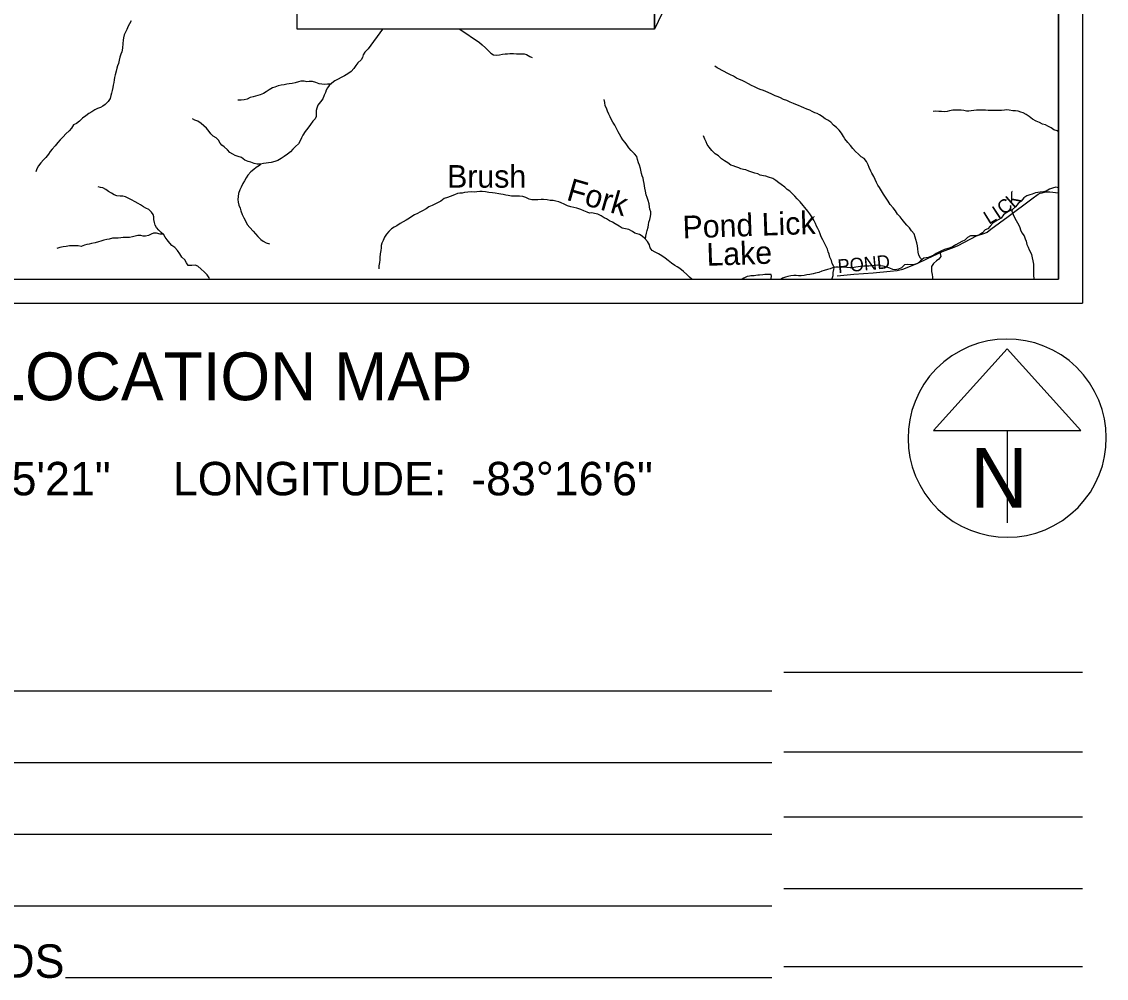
# Model space of a CAD drawing. Extents: x 0 to 34, y 0 to 22.
# Drawn here: x 4.561 to 9.099, y 11.175 to 15.178 of the extents above; entities that cross this region are included whole.
import ezdxf

# ---------------------------------------------------------------- set-up
doc = ezdxf.new("R2010")
doc.units = 0
for name, color, linetype in [('Default', 7, 'Continuous'), ('GM_X_Minor_Lake', 7, 'Continuous'), ('GM_X_Minor_Lake_Text', 7, 'Continuous'), ('GM_X_Minor_River', 7, 'Continuous'), ('GM_X_Minor_River_Text', 7, 'Continuous'), ('GM_X_Township_Road', 7, 'Continuous'), ('GM_X_Township_Road_Text', 7, 'Continuous'), ('SH_Cut_Line', 7, 'Continuous'), ('SH_Data', 7, 'Continuous'), ('SH_Text', 7, 'Continuous')]:
    doc.layers.add(name, color=color, linetype=linetype)

msp = doc.modelspace()

# ---------------------------------------------------------------- linework, layer by layer
at = {"layer": 'Default'}
msp.add_lwpolyline([(2.4545, 17.2795), (2.4313, 15.0183), (2.4372, 14.2719), (2.4352, 14.1), (8.9, 14.1), (8.9, 18.9397)], dxfattribs=at)
at = {"layer": 'GM_X_Minor_Lake'}
msp.add_lwpolyline([(7.6973, 14.1), (7.6976, 14.1032), (7.6984, 14.1127), (7.6969, 14.1207), (7.6886, 14.1207), (7.6802, 14.1204), (7.6711, 14.1197), (7.6616, 14.1186), (7.649, 14.1175), (7.641, 14.1168), (7.633, 14.1157), (7.6266, 14.115), (7.6209, 14.1147), (7.6117, 14.114), (7.606, 14.1136), (7.5969, 14.1118), (7.5885, 14.1073), (7.5824, 14.1042), (7.5756, 14.1)], dxfattribs=at)
at = {"layer": 'GM_X_Minor_River'}
for points in [[(5.0199, 15.1817), (5.013, 15.1696), (5.0076, 15.1597), (5.001, 15.1453), (4.9953, 15.1336), (4.9899, 15.123), (4.9868, 15.1109), (4.9859, 15.1014), (4.9851, 15.0869), (4.9827, 15.0672), (4.9803, 15.052), (4.9764, 15.0422), (4.9722, 15.0297), (4.9698, 15.0175), (4.9659, 15.0035), (4.9624, 14.9929), (4.9601, 14.983), (4.9566, 14.9717), (4.9527, 14.9561), (4.9504, 14.9444), (4.9484, 14.9341), (4.9472, 14.9239), (4.9448, 14.9121), (4.9429, 14.9026), (4.9394, 14.8901), (4.9374, 14.8787), (4.9343, 14.8689), (4.9312, 14.8567), (4.9231, 14.8435), (4.9113, 14.8322), (4.9013, 14.8243), (4.891, 14.8194), (4.8781, 14.8145), (4.8678, 14.8089), (4.8544, 14.8002), (4.8418, 14.7938), (4.8292, 14.784), (4.8159, 14.7739), (4.8029, 14.7618), (4.7903, 14.7527), (4.7781, 14.746), (4.7696, 14.7327), (4.7597, 14.7214), (4.7459, 14.7089), (4.7344, 14.6965), (4.7229, 14.6836), (4.7133, 14.6719), (4.7011, 14.6587), (4.6888, 14.6451), (4.6808, 14.6345), (4.6735, 14.6243), (4.6628, 14.6095), (4.6532, 14.6001), (4.6417, 14.5876), (4.6318, 14.5748), (4.6248, 14.5619), (4.6202, 14.5498)], [(6.071, 15.147), (6.0105, 15.0644), (5.9971, 15.0508), (5.9906, 15.0387), (5.9867, 15.0289), (5.9813, 15.0183), (5.9683, 15.0062), (5.9599, 14.9952), (5.9511, 14.9816), (5.9396, 14.9695), (5.9255, 14.9593), (5.9125, 14.9514), (5.8984, 14.9443), (5.8854, 14.9375), (5.8721, 14.9304), (5.8591, 14.9206), (5.8472, 14.9112), (5.8415, 14.9013), (5.8353, 14.8915), (5.8319, 14.882), (5.8268, 14.8699), (5.8207, 14.8555), (5.8118, 14.8423), (5.8004, 14.8286), (5.7957, 14.8161), (5.7941, 14.8063), (5.7929, 14.7941), (5.794, 14.782), (5.789, 14.771), (5.779, 14.7612), (5.7694, 14.7479), (5.7583, 14.7328), (5.7468, 14.7188), (5.7372, 14.7037), (5.7326, 14.6919), (5.7268, 14.6791), (5.7199, 14.667), (5.7073, 14.6556), (5.6954, 14.6443), (5.6855, 14.6341), (5.6732, 14.6232), (5.6595, 14.6138), (5.6465, 14.6051), (5.6335, 14.5976), (5.6202, 14.5923), (5.6046, 14.5886), (5.5939, 14.5875), (5.5844, 14.5865), (5.573, 14.5842), (5.5601, 14.582), (5.5471, 14.5821), (5.5339, 14.5848), (5.5206, 14.5895), (5.5088, 14.5933), (5.4952, 14.5984), (5.4812, 14.6098), (5.4671, 14.6145), (5.4543, 14.6187), (5.4448, 14.6233), (5.4327, 14.6302), (5.4225, 14.6413), (5.4089, 14.6539), (5.399, 14.6608), (5.3919, 14.6703), (5.3847, 14.6821), (5.3756, 14.6917), (5.3631, 14.699), (5.3526, 14.7089), (5.3465, 14.7188), (5.3352, 14.7322)], [(6.3947, 15.147), (6.4771, 15.0906), (6.4885, 15.0807), (6.5013, 15.0685), (6.5149, 15.0562), (6.5244, 15.0467), (6.5353, 15.0394), (6.5479, 15.0382), (6.5604, 15.04), (6.5726, 15.0423), (6.584, 15.0441), (6.5935, 15.044), (6.6034, 15.0444), (6.6186, 15.045), (6.6312, 15.0442), (6.6414, 15.0438), (6.6513, 15.0441), (6.6638, 15.0429), (6.6741, 15.0409), (6.687, 15.0321), (6.6968, 15.0283)], [(8.3282, 14.1824), (8.322, 14.1882), (8.3148, 14.2004), (8.3119, 14.2137), (8.3112, 14.2274), (8.309, 14.2407), (8.306, 14.2532), (8.3019, 14.2665), (8.2997, 14.276), (8.2949, 14.2901), (8.2847, 14.3023), (8.2764, 14.3149), (8.2654, 14.3271), (8.2564, 14.3367), (8.2454, 14.3508), (8.2375, 14.3611), (8.2258, 14.3729), (8.2179, 14.3859), (8.2074, 14.3992), (8.1949, 14.4126), (8.1862, 14.4263), (8.178, 14.44), (8.1674, 14.4568), (8.1588, 14.4705), (8.1505, 14.4842), (8.143, 14.4945), (8.1381, 14.5052), (8.1321, 14.517), (8.1261, 14.5303), (8.1189, 14.5437), (8.1137, 14.5532), (8.1077, 14.5673), (8.1024, 14.5794), (8.0961, 14.5928), (8.0863, 14.605), (8.0734, 14.6123), (8.062, 14.6233), (8.0496, 14.6348), (8.039, 14.6478), (8.0296, 14.6604), (8.0186, 14.673), (8.0058, 14.6875), (7.9998, 14.6981), (7.9919, 14.7115), (7.9813, 14.7244), (7.97, 14.7348), (7.9579, 14.7447), (7.9466, 14.7569), (7.9341, 14.7653), (7.9235, 14.7722), (7.911, 14.7818), (7.8992, 14.7887), (7.8898, 14.7937), (7.8799, 14.7972), (7.8689, 14.8022), (7.8591, 14.8075), (7.8466, 14.8122), (7.8337, 14.8176), (7.8242, 14.8222), (7.8113, 14.8272), (7.8007, 14.831), (7.7901, 14.8364), (7.7768, 14.8418), (7.7624, 14.848), (7.7491, 14.853), (7.7362, 14.8591), (7.7268, 14.8637), (7.7135, 14.8684), (7.7002, 14.8745), (7.6847, 14.8822), (7.6748, 14.886), (7.6646, 14.8899), (7.6509, 14.8949), (7.6407, 14.8991), (7.627, 14.9061), (7.6149, 14.9107), (7.602, 14.918), (7.5865, 14.9264), (7.5755, 14.9318), (7.5645, 14.936), (7.5524, 14.9418), (7.5391, 14.9495), (7.5266, 14.956), (7.513, 14.9621), (7.5005, 14.9694), (7.4717, 14.9848), (7.4618, 14.9917)], [(5.8538, 14.9164), (5.8408, 14.9165), (5.8286, 14.9154), (5.8165, 14.9167), (5.8059, 14.9182), (5.7922, 14.9229), (5.7782, 14.9279), (5.7645, 14.928), (5.7538, 14.9269), (5.7436, 14.9296), (5.7295, 14.9285), (5.7192, 14.9259), (5.7063, 14.9222), (5.6934, 14.92), (5.6812, 14.9178), (5.6709, 14.916), (5.6595, 14.9138), (5.6469, 14.9119), (5.6344, 14.909), (5.621, 14.9045), (5.6107, 14.9019), (5.5974, 14.8928), (5.5836, 14.8842), (5.573, 14.8774), (5.5585, 14.8714), (5.549, 14.8692), (5.5394, 14.8666), (5.5299, 14.8636), (5.5177, 14.861), (5.5048, 14.8543), (5.4922, 14.8517), (5.4793, 14.8502), (5.4664, 14.8503)], [(7.1711, 14.2681), (7.1734, 14.2801), (7.1757, 14.2934), (7.1781, 14.3044), (7.1831, 14.3177), (7.1835, 14.3283), (7.1855, 14.3397), (7.189, 14.3503), (7.1925, 14.3632), (7.1937, 14.3727), (7.193, 14.3825), (7.1897, 14.3932), (7.1878, 14.4027), (7.1868, 14.4156), (7.1827, 14.4293), (7.1778, 14.443), (7.1745, 14.4533), (7.1708, 14.4692), (7.1686, 14.4818), (7.1675, 14.4917), (7.1664, 14.5012), (7.1631, 14.5137), (7.1612, 14.5236), (7.1579, 14.5331), (7.1553, 14.543), (7.1508, 14.5643), (7.146, 14.5776), (7.1422, 14.5879), (7.1385, 14.6012), (7.1352, 14.6138), (7.1257, 14.6252), (7.1118, 14.6397), (7.1023, 14.6496), (7.0933, 14.6622), (7.0861, 14.6725), (7.0759, 14.6843), (7.0699, 14.6943), (7.062, 14.7068), (7.0564, 14.7175), (7.0504, 14.7316), (7.0425, 14.7453), (7.0353, 14.7571), (7.0278, 14.7708), (7.0229, 14.7803), (7.0177, 14.7906), (7.0117, 14.8032), (7.008, 14.8165), (7.0031, 14.826), (7.0013, 14.8405), (6.9979, 14.8526)], [(8.9, 14.7176), (8.894, 14.7208), (8.8804, 14.7262), (8.8683, 14.7339), (8.8546, 14.7412), (8.8452, 14.7461), (8.8326, 14.7496), (8.8194, 14.7558), (8.8053, 14.7612), (8.7902, 14.7704), (8.7762, 14.7807), (8.7645, 14.7899), (8.7519, 14.796), (8.7421, 14.7999), (8.7303, 14.8038), (8.7189, 14.8053), (8.7079, 14.8054), (8.6935, 14.8074), (8.6836, 14.809), (8.6737, 14.8075), (8.6615, 14.8064), (8.652, 14.8061), (8.6186, 14.8063), (8.6049, 14.8071), (8.5935, 14.8076), (8.5566, 14.8078), (8.5445, 14.8067), (8.5342, 14.8049), (8.5235, 14.8034), (8.514, 14.8038), (8.5026, 14.8058), (8.4924, 14.8074), (8.4814, 14.8074), (8.4673, 14.8079), (8.4567, 14.8076), (8.4433, 14.8046), (8.4334, 14.8016), (8.4235, 14.8013), (8.4099, 14.8021), (8.3981, 14.8022), (8.3863, 14.8034), (8.3749, 14.802)], [(5.3352, 14.7322), (5.3239, 14.7417), (5.3125, 14.752), (5.2989, 14.7616), (5.2856, 14.7659), (5.2762, 14.7712)], [(7.9626, 14.1497), (7.9587, 14.153), (7.9527, 14.166), (7.949, 14.1789), (7.943, 14.1926), (7.9393, 14.2048), (7.9363, 14.2143), (7.9326, 14.2265), (7.9262, 14.2398), (7.9194, 14.2535), (7.9134, 14.2649), (7.9066, 14.2783), (7.9025, 14.2908), (7.8984, 14.3011), (7.8924, 14.3121), (7.8875, 14.3228), (7.8823, 14.3338), (7.8763, 14.3479), (7.8673, 14.3609), (7.8594, 14.3746), (7.8511, 14.3853), (7.8382, 14.3998), (7.8311, 14.4093), (7.8186, 14.4238), (7.8065, 14.4364), (7.7956, 14.4483), (7.7865, 14.4578), (7.7752, 14.4689), (7.7646, 14.4765), (7.754, 14.4853), (7.7393, 14.4968), (7.7294, 14.5041), (7.7162, 14.5129), (7.7048, 14.5221), (7.6858, 14.5275), (7.6745, 14.5314), (7.6646, 14.5325), (7.6517, 14.5357), (7.6415, 14.5414), (7.6286, 14.5445), (7.616, 14.548), (7.6043, 14.5519), (7.591, 14.5576), (7.5808, 14.56), (7.5709, 14.5623), (7.5614, 14.5658), (7.5493, 14.5704), (7.5379, 14.5747), (7.528, 14.5781), (7.5152, 14.5877), (7.5023, 14.5957), (7.4898, 14.6042), (7.4762, 14.6164), (7.4629, 14.6252), (7.449, 14.6386), (7.4384, 14.6523), (7.4294, 14.6645), (7.4245, 14.6748), (7.4196, 14.687), (7.4136, 14.7003)], [(5.5638, 14.5827), (5.557, 14.5764), (5.5429, 14.5677), (5.5329, 14.559), (5.52, 14.5504), (5.5077, 14.5356), (5.5012, 14.5243), (5.4931, 14.5118), (5.487, 14.5012), (5.4793, 14.4849), (5.4742, 14.4747), (5.4692, 14.4595), (5.4665, 14.4462), (5.4664, 14.4341), (5.4678, 14.4234), (5.4704, 14.4109), (5.4749, 14.398), (5.4779, 14.3869), (5.4835, 14.3713), (5.4906, 14.3576), (5.4981, 14.3443), (5.5053, 14.3298), (5.5162, 14.3161), (5.5305, 14.3019), (5.5403, 14.2897), (5.549, 14.2798), (5.5619, 14.2668), (5.5717, 14.2596), (5.5846, 14.2527), (5.5979, 14.248)], [(4.9735, 14.4483), (4.9598, 14.4495), (4.9484, 14.4537), (4.9374, 14.4606), (4.9242, 14.4679), (4.9139, 14.4756), (4.9011, 14.4821), (4.8916, 14.4848), (4.8817, 14.4864)], [(8.9, 14.4825), (8.8876, 14.4858), (8.8746, 14.4809), (8.8617, 14.4772), (8.848, 14.4693), (8.8362, 14.4667), (8.8225, 14.4641), (8.8129, 14.463), (8.8031, 14.4612), (8.7897, 14.4567), (8.7798, 14.4533), (8.7669, 14.4492), (8.7539, 14.4413), (8.7432, 14.4273), (8.7305, 14.4172), (8.7198, 14.4035), (8.7072, 14.3926), (8.6935, 14.3855), (8.6801, 14.3783), (8.6694, 14.3693), (8.6598, 14.3564), (8.6469, 14.3489), (8.6369, 14.3436), (8.624, 14.335), (8.614, 14.3221), (8.6033, 14.3115), (8.5926, 14.307), (8.5819, 14.2946), (8.5704, 14.287), (8.5575, 14.2826), (8.5453, 14.2822), (8.5316, 14.2823), (8.5179, 14.2752), (8.5076, 14.2639)], [(5.3478, 14.1), (5.3461, 14.1067), (5.3378, 14.1192), (5.3242, 14.1315), (5.3117, 14.1426), (5.2989, 14.1544), (5.2867, 14.159), (5.2727, 14.1572), (5.2586, 14.1584), (5.2507, 14.1695), (5.2435, 14.1813), (5.2314, 14.1931), (5.2224, 14.2061), (5.213, 14.2202), (5.2028, 14.2324), (5.1899, 14.2408), (5.1816, 14.2515), (5.1703, 14.2656), (5.1624, 14.2759), (5.156, 14.2855), (5.1447, 14.2962), (5.1349, 14.305), (5.1258, 14.3164), (5.1205, 14.3267), (5.1164, 14.3381), (5.1146, 14.3503), (5.1139, 14.3617), (5.1113, 14.3712), (5.1049, 14.3807), (5.0932, 14.3918), (5.0815, 14.3979), (5.0716, 14.4037), (5.0587, 14.4117), (5.0489, 14.4171), (5.036, 14.424), (5.0209, 14.4328), (4.9959, 14.4451), (4.9852, 14.4475), (4.9735, 14.4483)], [(7.3647, 14.1), (7.3559, 14.1089), (7.3438, 14.1204), (7.3306, 14.1323), (7.3147, 14.1453), (7.3037, 14.1518), (7.2938, 14.1583), (7.2798, 14.1671), (7.2666, 14.1782), (7.2541, 14.1878), (7.2401, 14.1977), (7.2257, 14.2061), (7.2117, 14.2138), (7.1992, 14.2207), (7.1905, 14.2314), (7.1883, 14.2447), (7.1801, 14.2588), (7.1684, 14.271), (7.1578, 14.281), (7.146, 14.2879), (7.1362, 14.2898), (7.1263, 14.2937), (7.1165, 14.3002), (7.1021, 14.3079), (7.0876, 14.311), (7.0744, 14.3145), (7.0611, 14.3225), (7.0444, 14.3325), (7.0327, 14.339), (7.0213, 14.3451), (7.0077, 14.3524), (6.9982, 14.3574), (6.9857, 14.3655), (6.9717, 14.3732), (6.9577, 14.3759), (6.9463, 14.3775), (6.9364, 14.3772), (6.9269, 14.381), (6.9136, 14.386), (6.9004, 14.3918), (6.8841, 14.3976), (6.8719, 14.3999), (6.8594, 14.403), (6.8457, 14.4077), (6.8306, 14.4142), (6.818, 14.42), (6.8086, 14.4238), (6.796, 14.4273), (6.7854, 14.4293), (6.7725, 14.4301), (6.76, 14.4325), (6.7448, 14.4344), (6.7345, 14.4337), (6.7204, 14.4323), (6.7094, 14.432), (6.6953, 14.4328), (6.6843, 14.4355), (6.6707, 14.4417), (6.6578, 14.4459), (6.6449, 14.4479), (6.6335, 14.4476), (6.624, 14.4473), (6.6111, 14.4481), (6.5962, 14.4505), (6.5867, 14.452), (6.5765, 14.4544), (6.5666, 14.4563), (6.5571, 14.4575), (6.5427, 14.4606), (6.5317, 14.4618), (6.5161, 14.4638), (6.5024, 14.4658), (6.488, 14.467), (6.4777, 14.4671), (6.4663, 14.4656), (6.4561, 14.4646), (6.4431, 14.4654), (6.4276, 14.4651), (6.4146, 14.4633), (6.404, 14.4607), (6.3941, 14.46), (6.3842, 14.4585), (6.3716, 14.4533), (6.3537, 14.4469), (6.3426, 14.4428), (6.3285, 14.4379), (6.3144, 14.4274), (6.3014, 14.4206), (6.2896, 14.4138), (6.2789, 14.4094), (6.2648, 14.403), (6.2534, 14.3954), (6.2377, 14.3868), (6.2274, 14.3812), (6.2171, 14.3759), (6.2046, 14.3691), (6.1943, 14.3631), (6.184, 14.3563), (6.1698, 14.3477), (6.1572, 14.3405)], [(8.706, 14.392), (8.7045, 14.3846), (8.7097, 14.3717), (8.7157, 14.3588), (8.7225, 14.3458), (8.733, 14.3268), (8.7375, 14.3172), (8.7405, 14.3073), (8.7465, 14.2944), (8.7552, 14.2818), (8.7604, 14.2689), (8.7634, 14.2594), (8.7671, 14.2461), (8.772, 14.2346), (8.7768, 14.2236), (8.7821, 14.2133), (8.7858, 14.2034), (8.7892, 14.1905), (8.7914, 14.1776), (8.7951, 14.1631), (8.7949, 14.1293), (8.7951, 14.1149), (8.7962, 14.105), (8.7962, 14.1)], [(6.1572, 14.3405), (6.145, 14.333), (6.1309, 14.3236), (6.1202, 14.3176), (6.1092, 14.3108), (6.0973, 14.3006), (6.0877, 14.2889), (6.0797, 14.2757), (6.0735, 14.2617), (6.0681, 14.2514), (6.0658, 14.2419), (6.0649, 14.2317), (6.0641, 14.2203), (6.0617, 14.2067), (6.0605, 14.1918), (6.0597, 14.1816), (6.0585, 14.1698), (6.0553, 14.1566), (6.0553, 14.1444)], [(5.153, 14.2883), (5.1408, 14.2894), (5.126, 14.2925), (5.1123, 14.2929), (5.1028, 14.2892), (5.0921, 14.2839), (5.0792, 14.2802), (5.0697, 14.2806), (5.0595, 14.2837), (5.0469, 14.2834), (5.0359, 14.2801), (5.0252, 14.2775), (5.013, 14.2749), (5.0028, 14.2753), (4.9864, 14.275), (4.9758, 14.274), (4.9655, 14.2725), (4.9533, 14.2722), (4.9408, 14.2715), (4.9274, 14.2682), (4.9179, 14.2663), (4.9046, 14.2634), (4.8932, 14.26), (4.8829, 14.2574), (4.8692, 14.2529), (4.854, 14.2496), (4.8441, 14.2477), (4.8342, 14.2463), (4.8243, 14.2422), (4.8109, 14.2377), (4.7973, 14.2397), (4.7843, 14.2405), (4.7733, 14.2402), (4.7612, 14.2399), (4.7482, 14.2377), (4.7353, 14.2358), (4.7208, 14.2325), (4.7079, 14.2295)], [(8.5076, 14.2639), (8.495, 14.2582), (8.4824, 14.2515), (8.4694, 14.2439), (8.4557, 14.2353), (8.4462, 14.2323), (8.4366, 14.2282), (8.4229, 14.2241), (8.4103, 14.2196), (8.3981, 14.2136), (8.3878, 14.2079), (8.3775, 14.2015), (8.3673, 14.197), (8.3547, 14.1918), (8.3452, 14.1892), (8.3356, 14.1881), (8.3219, 14.1775), (8.3097, 14.1666), (8.2975, 14.1621), (8.283, 14.1611), (8.2689, 14.1615), (8.2556, 14.1601), (8.2423, 14.1484), (8.2293, 14.142), (8.2163, 14.1398), (8.2061, 14.141), (8.1936, 14.1471), (8.1811, 14.151), (8.1655, 14.1549), (8.1541, 14.1568), (8.1412, 14.1588), (8.1306, 14.1581), (8.1188, 14.1563), (8.1062, 14.1556), (8.0959, 14.1553), (8.0853, 14.1546), (8.0708, 14.1531), (8.0606, 14.1521), (8.0507, 14.1502), (8.0381, 14.1476), (8.0271, 14.1473), (8.0142, 14.15), (8.0043, 14.1505), (7.9906, 14.149), (7.9777, 14.1503), (7.9678, 14.1511), (7.9541, 14.1473), (7.9446, 14.1444), (7.9324, 14.1406), (7.9194, 14.1365), (7.9092, 14.1339), (7.8966, 14.1287), (7.8832, 14.125), (7.8726, 14.1227), (7.8593, 14.1202), (7.8463, 14.118), (7.8353, 14.1165), (7.8231, 14.115), (7.8109, 14.1144), (7.8015, 14.1155), (7.7919, 14.1156), (7.7794, 14.1145), (7.7665, 14.1116), (7.7569, 14.109), (7.744, 14.1041), (7.7383, 14.1)], [(8.4055, 14.2172), (8.4042, 14.2078), (8.4068, 14.1957), (8.398, 14.184), (8.3884, 14.1779), (8.3769, 14.1666), (8.3685, 14.1537), (8.3673, 14.1443), (8.3684, 14.1332), (8.3706, 14.1199), (8.3724, 14.1089), (8.3721, 14.1)], [(7.9598, 14.1489), (7.9582, 14.1409), (7.9555, 14.1287), (7.9546, 14.1151), (7.9504, 14.1022), (7.9498, 14.1)]]:
    msp.add_lwpolyline(points, dxfattribs=at)
at = {"layer": 'GM_X_Township_Road'}
msp.add_lwpolyline([(7.9737, 14.1147), (8.0429, 14.1212), (8.124, 14.1274), (8.1952, 14.1334), (8.2245, 14.1372), (8.248, 14.1419), (8.3081, 14.1656), (8.351, 14.1866), (8.4142, 14.2158), (8.4633, 14.2338), (8.4789, 14.2416), (8.5561, 14.2814), (8.5907, 14.2929), (8.6003, 14.2979), (8.6163, 14.3102), (8.6882, 14.3634), (8.7875, 14.4368), (8.8145, 14.4556), (8.8231, 14.4599), (8.831, 14.4622), (8.8404, 14.4645), (8.8511, 14.466), (8.8636, 14.466), (8.9, 14.4624)], dxfattribs=at)
at = {"layer": 'SH_Cut_Line'}
msp.add_lwpolyline([(2.4352, 14.1), (8.9, 14.1), (8.9, 20.9), (2.4845, 20.9), (2.4809, 20.6393), (2.4757, 20.2566), (2.4573, 18.9074), (2.4581, 18.1825), (2.4581, 18.1772), (2.4586, 17.7785), (2.4545, 17.2795), (2.4313, 15.0183), (2.4372, 14.2719)], close=True, dxfattribs=at)
at = {"layer": 'SH_Data'}
for p, q in [((9, 21), (9, 14)), ((8.9, 20.9), (8.9, 14.1)), ((2.1, 14.1), (8.9, 14.1)), ((2, 14), (9, 14)), ((8.6845, 13.8091), (8.3769, 13.4678)), ((8.9921, 13.4678), (8.6845, 13.8091)), ((8.3769, 13.4678), (8.9921, 13.4678)), ((8.6845, 13.4678), (8.6845, 13.0811)), ((8.6845, 13.4353), (8.6845, 13.4353)), ((8.6845, 13.4353), (8.6845, 13.4353)), ((7.75, 12.4553), (9, 12.4553)), ((7.7, 12.3767), (4.4937, 12.3767)), ((9, 12.1207), (7.75, 12.1207)), ((7.7, 12.0767), (3.9895, 12.0767)), ((9, 11.8491), (7.75, 11.8491)), ((7.7, 11.7767), (3.6192, 11.7767)), ((9, 11.5491), (7.75, 11.5491)), ((7.7, 11.4767), (3.3288, 11.4767)), ((9, 11.2223), (7.75, 11.2223)), ((7.7, 11.1767), (4.7452, 11.1767))]:
    msp.add_line(p, q, dxfattribs=at)
msp.add_arc((8.6845, 13.4353), 0.4148, 129.7798, 129.7633, dxfattribs=at)
at = {"layer": 'SH_Text'}
for points in [[(7.2097, 15.6335), (7.6704, 16.1119), (7.2097, 15.147)], [(5.7139, 15.6335), (7.2097, 15.6335), (7.2097, 15.147), (5.7139, 15.147)]]:
    msp.add_lwpolyline(points, close=True, dxfattribs=at)

# ---------------------------------------------------------------- texts
at = {"layer": 'GM_X_Minor_Lake_Text'}
for s, p in [('Pond Lick', (7.3281, 14.2709)), ('Lake', (7.4279, 14.1562))]:
    msp.add_text(s, height=0.0947, rotation=2.0027, dxfattribs=at).set_placement(p)
at = {"layer": 'GM_X_Minor_River_Text'}
for s, rotation, p in [('Brush', 0.0017, (6.3414, 14.4834)), ('Fork', 344.0006, (6.8367, 14.4331))]:
    msp.add_text(s, height=0.0947, rotation=rotation, dxfattribs=at).set_placement(p)
at = {"layer": 'GM_X_Township_Road_Text'}
for s, height, rotation, p in [('C', 0.0568, 37.7208, (8.6694, 14.3666)), ('K', 0.0568, 41.2927, (8.7092, 14.3976)), ('I', 0.0568, 33.4551, (8.6461, 14.3511)), ('L', 0.0568, 31.6892, (8.6084, 14.3277)), ('POND', 0.05682, 5.4865, (7.978, 14.1259))]:
    msp.add_text(s, height=height, rotation=rotation, dxfattribs=at).set_placement(p)
at = {"layer": 'SH_Data'}
msp.add_text('N', height=0.25, dxfattribs=at).set_placement((8.5292, 13.144))
at = {"layer": 'SH_Text'}
for s, height, p in [('LOCATION MAP', 0.2, (4.4269, 13.5938)), ('LATITUDE:  38°45\'21"     LONGITUDE:  -83°16\'6"', 0.14, (3.071, 13.1959)), ('COUNTY & TOWNSHIP ROADS', 0.14, (1.9944, 11.1767))]:
    msp.add_text(s, height=height, dxfattribs=at).set_placement(p)

doc.saveas('drawing.dxf')
